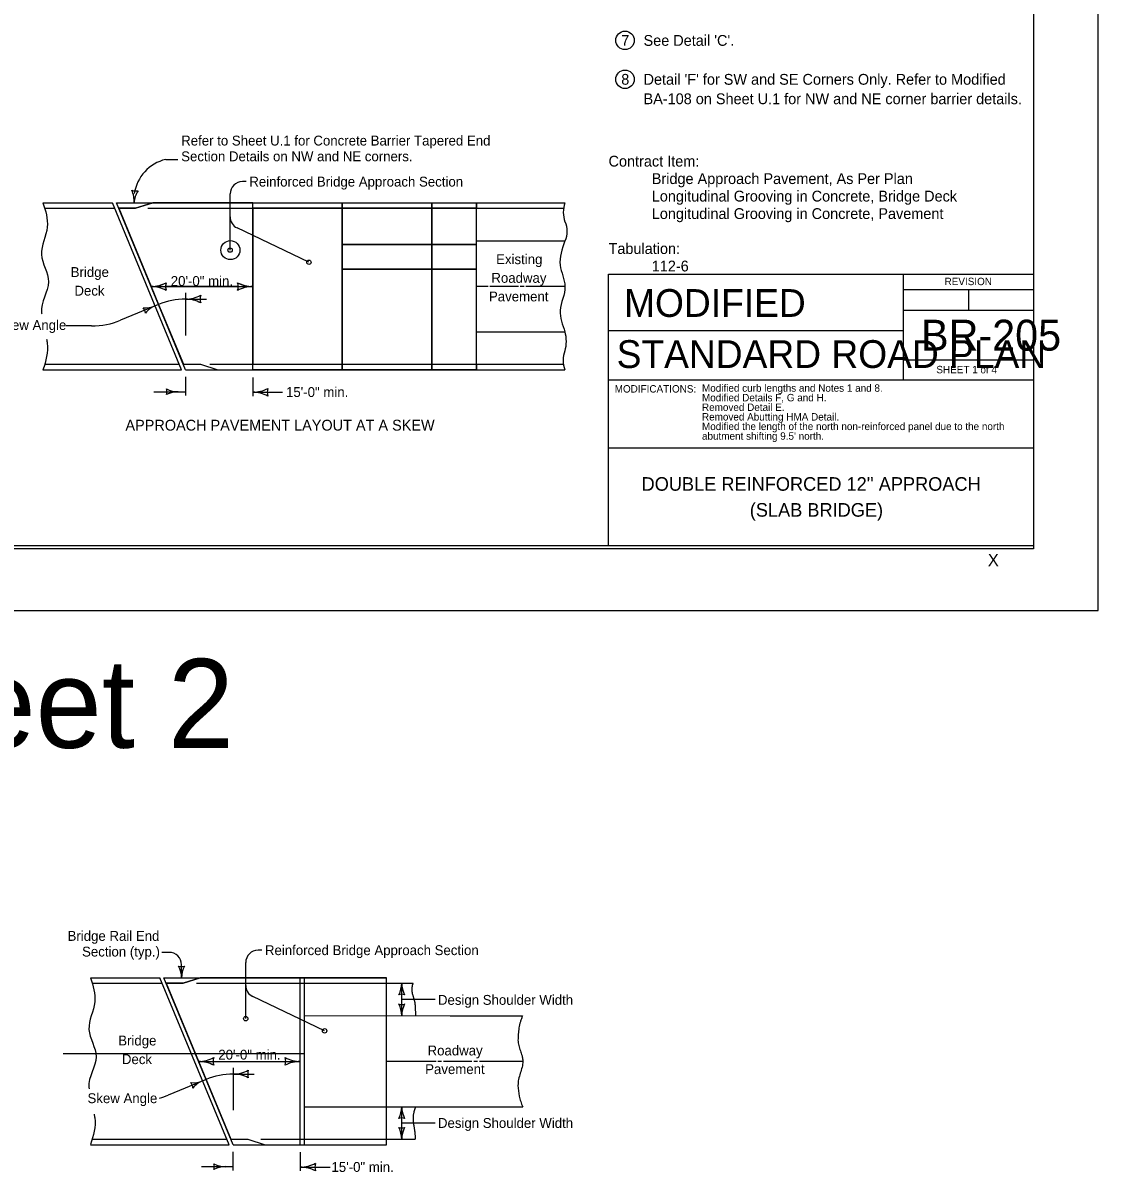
# Model space of a CAD drawing. Extents: x 10028 to 81668, y 6395 to 11634.
# Drawn here: x 15231 to 16972, y 6915 to 8776 of the extents above; entities that cross this region are included whole.
import ezdxf

# ---------------------------------------------------------------- set-up
doc = ezdxf.new("R2010")
doc.units = 0
for name, color, linetype in [('Constructions', 7, 'Continuous'), ('Default', 7, 'Continuous'), ('dsnCellElements', 7, 'Continuous'), ('dsnPaintPlaceStopLineWhite', 7, 'Continuous'), ('dsnstdblockInterim', 7, 'Continuous'), ('dsnStdBlockNotModified', 7, 'Continuous'), ('dsnStdDimension', 7, 'Continuous'), ('dsnStdTextLabel', 7, 'Continuous'), ('dsnStgShadingPropPav', 7, 'Continuous'), ('dsnTextNote', 7, 'Continuous'), ('ShtPlotIdentification', 7, 'Continuous'), ('TextAlignmentSml', 7, 'Continuous')]:
    doc.layers.add(name, color=color, linetype=linetype)

msp = doc.modelspace()

# ---------------------------------------------------------------- linework, layer by layer
at = {"layer": 'Default'}
msp.add_lwpolyline([(13732.5, 9944), (16867.5, 9944), (16867.5, 7924), (13732.5, 7924)], close=True, dxfattribs=at)
at = {"layer": 'dsnCellElements'}
for p, q in [((15893.2, 8475.8), (15748.3, 8475.8)), ((15748.3, 8475.8), (15748.3, 8417.2)), ((15893.2, 8417.2), (15893.2, 8475.8)), ((15965.7, 8475.8), (15893.2, 8475.8)), ((15893.2, 8475.8), (15893.2, 8417.2)), ((15965.7, 8417.2), (15965.7, 8475.8)), ((15893.2, 8417.2), (15748.3, 8417.2)), ((15748.3, 8417.2), (15748.3, 8377.2)), ((15748.3, 8417.2), (15893.2, 8417.2)), ((15893.2, 8377.2), (15893.2, 8417.2)), ((15893.2, 8417.2), (15893.2, 8417.2)), ((15965.7, 8417.2), (15893.2, 8417.2)), ((15893.2, 8417.2), (15893.2, 8377.2)), ((15893.2, 8417.2), (15965.7, 8417.2)), ((15965.7, 8377.2), (15965.7, 8417.2)), ((15748.3, 8377.2), (15748.3, 8223)), ((15748.3, 8377.2), (15893.2, 8377.2)), ((15893.2, 8223), (15893.2, 8377.2)), ((15893.2, 8377.2), (15893.2, 8223)), ((15965.7, 8377.2), (15893.2, 8377.2)), ((15893.2, 8377.2), (15965.7, 8377.2)), ((15965.7, 8223), (15965.7, 8377.2)), ((15748.3, 8223), (15893.2, 8223)), ((15893.2, 8223), (15965.7, 8223))]:
    msp.add_line(p, q, dxfattribs=at)
for points in [[(15603.4, 8484.5), (15748.3, 8484.5), (15748.3, 8475.8), (15628.4, 8475.8), (15603.4, 8475.8)], [(15893.2, 8484.4), (15893.2, 8475.8), (15748.3, 8475.8), (15748.3, 8484.5)], [(15965.7, 8484.4), (15965.7, 8475.8), (15893.2, 8475.8), (15893.2, 8484.4)], [(15748.3, 8214.1), (15603.4, 8214.1), (15603.4, 8223), (15610.7, 8223), (15653.9, 8223), (15701.6, 8223), (15748.3, 8223)], [(15748.3, 8214.1), (15748.3, 8223), (15893.2, 8223), (15893.2, 8214.1)], [(15965.7, 8214.1), (15893.2, 8214.1), (15893.2, 8223), (15965.7, 8223)]]:
    msp.add_lwpolyline(points, close=True, dxfattribs=at)
msp.add_lwpolyline([(15893.2, 8377.2), (15893.2, 8377.2), (15748.3, 8377.2)], dxfattribs=at)
at = {"layer": 'dsnstdblockInterim'}
msp.add_lwpolyline([(13732.5, 9939), (16867.5, 9939), (16867.5, 7929), (13732.5, 7929)], close=True, dxfattribs=at)
at = {"layer": 'dsnStdBlockNotModified'}
for centre, radius, start, end in [((15413.9, 8520), 16.4, 247.9002, 283.3669), ((15368.8, 8487.7), 42.5, 355.6335, 23.706), ((15453.6, 8481.3), 42.5, 147.561, 175.6335)]:
    msp.add_arc(centre, radius, start, end, dxfattribs=at)
at = {"layer": 'dsnStdDimension'}
msp.add_lwpolyline([(13628, 7824.5), (16972, 7824.5), (16972, 10408.5), (13628, 10408.5)], close=True, dxfattribs=at)
at = {"layer": 'dsnStgShadingPropPav'}
for centre in [(15566.8, 8407.9), (15694.4, 8388.2), (15592.1, 7163.5), (15719.8, 7143.8)]:
    msp.add_circle(centre, 3.54, dxfattribs=at)
at = {"layer": 'ShtPlotIdentification'}
for p, q in [((15462.5, 8554.6), (15482, 8554.6)), ((15592.9, 8518.8), (15586.8, 8518.8)), ((15263.8, 8484.5), (15375.9, 8484.5)), ((15488.1, 8214.1), (15376.1, 8484.5)), ((15494.7, 8214.1), (15382.8, 8484.5)), ((15382.8, 8484.5), (15603.4, 8484.5)), ((15441.5, 8484.5), (15413.8, 8475.8)), ((15413.8, 8475.8), (15441.5, 8484.5)), ((15603.4, 8484.5), (15441.5, 8484.5)), ((15566.8, 8407.9), (15566.8, 8498.8)), ((15603.4, 8423.1), (15603.4, 8484.5)), ((15603.4, 8223), (15603.4, 8484.5)), ((15603.4, 8484.5), (15965.7, 8484.4)), ((15748.3, 8214.1), (15748.3, 8484.5)), ((15893.2, 8214.1), (15893.2, 8484.4)), ((15965.7, 8214.1), (15965.7, 8484.4)), ((15965.7, 8484.4), (16109, 8484.4)), ((15266.7, 8475.8), (15379.6, 8475.8)), ((15386.3, 8475.8), (15413.8, 8475.8)), ((15413.8, 8475.8), (15386.4, 8475.8)), ((15386.4, 8475.8), (15438.9, 8349)), ((15433.4, 8475.8), (16106.8, 8475.8)), ((15748.3, 8475.8), (15603.4, 8475.8)), ((15965.7, 8223), (15965.7, 8475.8)), ((15694.4, 8388.2), (15578.1, 8443.8)), ((15965.7, 8423), (16109, 8423)), ((15438.8, 8349), (15603.4, 8349)), ((15438.9, 8349), (15439.5, 8349)), ((15462.4, 8349), (15579.8, 8349)), ((15579.8, 8349), (15462.4, 8349)), ((15494.7, 8338.6), (15494.7, 8269.9)), ((15602.7, 8349), (15603.4, 8349)), ((15603.4, 8349), (15603.4, 8349)), ((15603.4, 8349), (15603.4, 8281)), ((15450.9, 8319.9), (15389.5, 8294.4)), ((15494.7, 8328.6), (15528.7, 8328.6)), ((15342.5, 8285.1), (15301.1, 8285.1)), ((15603.4, 8281), (15603.4, 8223)), ((15603.4, 8214.1), (15603.4, 8281)), ((15965.7, 8275.5), (16109, 8275.5)), ((15263.8, 8214.1), (15488.1, 8214.1)), ((15266.5, 8223), (15484.4, 8223)), ((15491.1, 8223), (15518.6, 8223)), ((15491.1, 8223), (15518.6, 8223)), ((15494.7, 8214.1), (15603.4, 8214.1)), ((15518.6, 8223), (15546.8, 8214.1)), ((15518.6, 8223), (15546.8, 8214.1)), ((15533.8, 8223), (16106.5, 8223)), ((15546.8, 8214.1), (15603.4, 8214.1)), ((15603.4, 8223), (15653.9, 8223)), ((15603.4, 8214.1), (15965.7, 8214.1)), ((15653.9, 8223), (15653.9, 8223)), ((15965.7, 8214.1), (16109, 8214)), ((15494.4, 8202.6), (15494.4, 8172.4)), ((15603.4, 8201.9), (15603.4, 8171.7)), ((15443.4, 8178.6), (15494.4, 8178.6)), ((15603.4, 8177.8), (15651.8, 8177.8)), ((15468.1, 7270.9), (15456.3, 7270.9)), ((15618.3, 7274.4), (15612.1, 7274.4)), ((15488.1, 7229.8), (15488.1, 7250.9)), ((15592.1, 7163.5), (15592.1, 7254.4)), ((15340.8, 7229.8), (15452.9, 7229.8)), ((15343.6, 7221.1), (15456.6, 7221.1)), ((15565, 6959.4), (15453, 7229.8)), ((15571.7, 6959.4), (15459.7, 7229.8)), ((15459.7, 7229.8), (15820.1, 7229.8)), ((15463.2, 7221.1), (15490.8, 7221.1)), ((15490.8, 7221.1), (15518.5, 7229.8)), ((15512.3, 7221.1), (15862.9, 7221.1)), ((15680.4, 7168.4), (15680.4, 7229.8)), ((15687, 6959.4), (15687, 7229.8)), ((15820.1, 6959.4), (15820.1, 7229.8)), ((15844.6, 7168.4), (15844.6, 7221.1)), ((15719.8, 7143.8), (15603.5, 7199.4)), ((15844.6, 7194.8), (15898.6, 7194.8)), ((15680.4, 7020.9), (15680.4, 7168.4)), ((15687, 7168.4), (15923, 7168.3)), ((15923, 7168.3), (16040.3, 7168.3)), ((15296.3, 7107.3), (15687.2, 7107.3)), ((15515.7, 7094.3), (15680.4, 7094.3)), ((15571.7, 7083.9), (15571.7, 7015.2)), ((15571.7, 7073.9), (15605.7, 7073.9)), ((15527.9, 7065.2), (15466.5, 7039.8)), ((15680.4, 6959.4), (15680.4, 7020.9)), ((15687, 7020.9), (15923, 7020.9)), ((15844.6, 6968.3), (15844.6, 7020.9)), ((15923, 7020.9), (16040.7, 7020.8)), ((15844.6, 6994.6), (15898.6, 6994.6)), ((15340.8, 6959.4), (15565, 6959.4)), ((15343.5, 6968.3), (15561.4, 6968.3)), ((15568, 6968.3), (15595.6, 6968.3)), ((15571.7, 6959.4), (15820.1, 6959.4)), ((15595.6, 6968.3), (15623.7, 6959.4)), ((15616.3, 6968.3), (15866.5, 6968.3)), ((15571.3, 6947.9), (15571.3, 6917.7)), ((15680.4, 6947.2), (15680.4, 6917)), ((15520.4, 6923.9), (15571.3, 6923.9)), ((15680.4, 6923.1), (15728.8, 6923.1))]:
    msp.add_line(p, q, dxfattribs=at)
for points in [[(15603.4, 8349), (15603.4, 8408.3), (15603.4, 8423.1), (15603.4, 8475.8), (15603.4, 8484.5)], [(15603.4, 8475.8), (15603.4, 8408.3), (15603.4, 8349)], [(15748.3, 8223), (15748.3, 8349.4), (15748.3, 8475.8)], [(15438.9, 8349), (15450.9, 8319.9), (15491.1, 8223)], [(15603.4, 8214.1), (15603.4, 8223), (15603.4, 8275.6), (15603.4, 8349)], [(15603.4, 8349), (15603.4, 8349)], [(15965.7, 8349.3), (15984.4, 8349.3)], [(15987.5, 8349.3), (16033.5, 8349.3)], [(16036.6, 8349.3), (16042.8, 8349.3)], [(16045.8, 8349.3), (16109, 8349.3)], [(15653.9, 8223), (15701.6, 8223), (15748.3, 8223)], [(15567.9, 6968.3), (15595.5, 6968.3), (15623.6, 6959.4), (15820.1, 6959.4), (15820.1, 7229.8), (15518.4, 7229.8), (15490.7, 7221.1), (15463.2, 7221.1), (15567.9, 6968.3)], [(15820.3, 7094.6), (15900.2, 7094.6)], [(15902.9, 7094.6), (15909.1, 7094.6)], [(15912.1, 7094.6), (15958.2, 7094.6)], [(15961.3, 7094.6), (15967.4, 7094.6)], [(15970.5, 7094.6), (16040.5, 7094.6)]]:
    msp.add_lwpolyline(points, dxfattribs=at)
for centre, radius in [((16206.2, 8747.5), 15), ((16206.2, 8684.5), 15), ((15567.2, 8407.9), 15.4), ((15567.2, 8407.9), 15.4), ((15566.8, 8407.9), 3.54)]:
    msp.add_circle(centre, radius, dxfattribs=at)
for centre, radius, start, end in [((15477.6, 8489.7), 66.7, 103.1177, 171.5172), ((15586.8, 8498.8), 20, 90, 180), ((16150.7, 8469), 44.5, 159.7913, 200.2087), ((15586.8, 8461.8), 20, 180, 244.4655), ((16078.8, 8438.3), 33.9, 333.04, 26.96), ((15438.8, 8401.2), 52.2, 270, 298.0725), ((15438.8, 8401.2), 52.2, 270.8433, 298.0725), ((15482.5, 8349), 20.2, 162.2666, 179.9839), ((15482.5, 8349), 20.2, 162.2666, 197.7334), ((15559.6, 8349), 20.2, 0.0161, 17.7334), ((15603.4, 8401.2), 52.2, 241.9275, 269.1567), ((15559.6, 8349), 20.2, 342.2666, 17.7334), ((15603.4, 8401.2), 52.2, 241.9275, 270), ((15438.8, 8296.7), 52.2, 61.9275, 90), ((15438.8, 8296.7), 52.2, 61.9275, 89.8364), ((15482.5, 8349), 20.2, 179.9839, 197.7334), ((15603.4, 8296.7), 52.2, 90.0176, 118.0725), ((15559.6, 8349), 20.2, 342.2666, 0.0161), ((15603.4, 8296.7), 52.2, 90, 118.0725), ((15603.4, 8401.2), 52.2, 269.9824, 270), ((15429.9, 8354.6), 40.2, 264.4275, 292.5), ((15460.6, 8280.4), 40.2, 112.5, 140.5725), ((15494.7, 8214.1), 114.5, 90, 112.5), ((15494.7, 8380.8), 52.2, 270, 298.0725), ((15494.7, 8380.8), 52.2, 270, 298.0725), ((15494.7, 8276.4), 52.2, 61.9275, 90), ((15494.7, 8276.4), 52.2, 61.9275, 90), ((15538.5, 8328.6), 20.2, 162.2666, 197.7334), ((15538.5, 8328.6), 20.2, 162.2666, 197.7334), ((15414.1, 8304.6), 15.5, 4.7666, 40.2333), ((15342.5, 8408), 122.9, 270, 292.5), ((16055.1, 8260.1), 56.1, 344.1047, 15.8953), ((16147.4, 8229.4), 41.4, 158.1771, 201.8229), ((15613.7, 8223), 40.2, 359.9859, 360), ((15448.9, 8178.6), 15.5, 342.2666, 17.7334), ((15482.6, 8218.7), 40.2, 241.9275, 270), ((15482.6, 8138.4), 40.2, 90, 118.0725), ((15603.4, 8230.1), 52.2, 270, 298.0725), ((15603.4, 8125.6), 52.2, 61.9275, 90), ((15647.2, 8177.8), 20.2, 162.2666, 197.7334), ((15468.1, 7250.9), 20, 0, 90), ((15612.1, 7254.4), 20, 90, 180), ((15488.1, 7263.5), 15.5, 252.2666, 287.7333), ((15448, 7229.8), 40.2, 360, 28.0725), ((15528.3, 7229.8), 40.2, 151.9275, 180), ((15804.4, 7221.1), 40.2, 331.9275, 360), ((15884.8, 7221.1), 40.2, 180, 208.0725), ((15612.1, 7217.4), 20, 180, 244.4655), ((15844.6, 7187.4), 15.5, 72.2666, 107.7334), ((15844.6, 7202), 15.5, 252.2666, 287.7333), ((15804.4, 7168.4), 40.2, 360, 28.0725), ((15884.8, 7168.4), 40.2, 151.9275, 180), ((15515.7, 7146.5), 52.2, 270, 298.0725), ((15515.7, 7042), 52.2, 61.9275, 90), ((15559.5, 7094.3), 20.2, 162.2666, 197.7334), ((15636.6, 7094.3), 20.2, 342.2666, 17.7334), ((15680.4, 7146.5), 52.2, 241.9275, 270), ((15680.4, 7042), 52.2, 90, 118.0725), ((15571.7, 6959.4), 114.5, 90, 112.5), ((15571.7, 7126.1), 52.2, 270, 298.0725), ((15571.7, 7126.1), 52.2, 270, 298.0725), ((15571.7, 7021.7), 52.2, 61.9275, 90), ((15571.7, 7021.7), 52.2, 61.9275, 90), ((15615.5, 7073.9), 20.2, 162.2666, 197.7334), ((15615.5, 7073.9), 20.2, 162.2666, 197.7334), ((15506.8, 7099.9), 40.2, 264.4275, 292.5), ((15491.1, 7049.9), 15.5, 4.7666, 40.2333), ((15537.6, 7025.7), 40.2, 112.5, 140.5725), ((15419.5, 7153.3), 122.9, 285.5345, 292.5), ((15804.4, 7020.9), 40.2, 331.9275, 360), ((15884.8, 7020.9), 40.2, 180, 208.0725), ((15844.6, 6987.2), 15.5, 72.2666, 107.7334), ((15844.6, 7002), 15.5, 252.2666, 287.7333), ((15804.4, 6968.3), 40.2, 360, 28.0725), ((15884.8, 6968.3), 40.2, 151.9275, 180), ((15525.9, 6923.9), 15.5, 342.2666, 17.7334), ((15559.6, 6964), 40.2, 241.9275, 270), ((15559.6, 6883.7), 40.2, 90, 118.0725), ((15680.4, 6975.4), 52.2, 270, 298.0725), ((15680.4, 6870.9), 52.2, 61.9275, 90), ((15724.2, 6923.1), 20.2, 162.2666, 197.7334)]:
    msp.add_arc(centre, radius, start, end, dxfattribs=at)
for points in [[(15263.8, 8484.5), (15270.7, 8445.3), (15261.4, 8400.9), (15272.7, 8356.6), (15261.4, 8307), (15261.7, 8304.7)], [(16109, 8423), (16101.2, 8383.3), (16109, 8349.2), (16101.2, 8310.1), (16109, 8275.5)], [(15269.5, 8263.7), (15270.7, 8257.5), (15263.8, 8214.1)], [(15340.8, 7229.8), (15347.6, 7190.6), (15338.3, 7146.2), (15349.7, 7101.9), (15338.3, 7052.3), (15338.6, 7050)], [(16040.3, 7168.3), (16038.4, 7163.4), (16036.8, 7158.4), (16034.5, 7148.5), (16033.3, 7138.5), (16033, 7133.6), (16032.9, 7128.6), (16033.2, 7124.4), (16034, 7120.1), (16036.7, 7111.6), (16039.4, 7103.1), (16040.5, 7096.7), (16040.6, 7095.6), (16040.7, 7094.6), (16040.4, 7089.7), (16039.4, 7084.8), (16036.6, 7075), (16033.9, 7065.2), (16033.1, 7060.3), (16032.9, 7055.4), (16035, 7038.1), (16037.3, 7029.4), (16038.8, 7025.1), (16040.7, 7020.8)], [(15346.4, 7009), (15347.6, 7002.8), (15340.8, 6959.5)]]:
    msp.add_spline(points, degree=3, dxfattribs=at)
for points in [[(15862.9, 7221.1), (15862.7, 7220.6), (15862.5, 7220.1), (15862.4, 7219.6), (15862.2, 7219.1), (15862.1, 7218.6), (15861.9, 7218.1), (15861.7, 7217.2), (15861.5, 7216.2), (15861.3, 7215.2), (15861.1, 7214.2), (15861, 7213.2), (15861, 7212.2), (15860.9, 7211.7), (15860.9, 7211.2), (15860.9, 7210.7), (15860.9, 7210.2), (15860.9, 7209.7), (15860.9, 7209.2), (15861, 7208.2), (15861.1, 7207.3), (15861.3, 7206.3), (15861.4, 7205.4), (15861.6, 7204.4), (15861.9, 7203.5), (15862.4, 7201.6), (15863, 7199.8), (15863.5, 7197.9), (15864.1, 7196), (15864.6, 7194.1), (15865.2, 7192.2), (15865.5, 7191.3), (15865.6, 7190.3), (15865.8, 7189.4), (15865.9, 7188.4), (15866.1, 7187.4), (15866.1, 7186.5), (15866.2, 7185), (15866.3, 7183.5), (15866.3, 7181.9), (15866.4, 7180.4), (15866.5, 7178.9), (15866.6, 7177.4), (15866.7, 7175.9), (15866.7, 7174.4), (15866.8, 7172.9), (15866.8, 7171.4), (15866.9, 7169.9), (15866.9, 7168.4)], [(15866.9, 7020.9), (15866.6, 7020), (15866.3, 7019.1), (15866, 7018.3), (15865.8, 7017.4), (15865.5, 7016.5), (15865.2, 7015.6), (15864.7, 7013.9), (15864.3, 7012.1), (15863.9, 7010.3), (15863.3, 7007.7), (15863, 7005.1), (15863, 7002.4), (15862.9, 7001.9), (15862.9, 7001.5), (15863, 7001.1), (15863, 7000.6), (15863, 7000.2), (15863, 6999.7), (15863.1, 6998.7), (15863.2, 6997.8), (15863.3, 6996.8), (15863.4, 6995.8), (15863.5, 6994.8), (15863.6, 6993.8), (15863.9, 6991.8), (15864.3, 6989.9), (15864.6, 6987.9), (15864.9, 6985.9), (15865.2, 6983.9), (15865.5, 6982), (15865.7, 6981), (15865.8, 6980), (15865.9, 6979), (15866, 6978), (15866.1, 6977), (15866.1, 6976), (15866.3, 6973.4), (15866.4, 6970.9), (15866.5, 6968.3)]]:
    msp.add_open_spline(points, degree=3, dxfattribs=at)
at = {"layer": 'TextAlignmentSml'}
for p, q in [((16656.6, 8369), (16656.6, 8277.7)), ((16656.6, 8344.1), (16867.5, 8344.1)), ((16762.1, 8344.1), (16762.1, 8310.9)), ((16656.6, 8310.9), (16867.5, 8310.9)), ((16179.5, 8277.7), (16656.6, 8277.7)), ((16656.6, 8277.7), (16656.6, 8197.7)), ((16867.5, 8229.9), (16656.6, 8229.9)), ((16179.5, 8197.7), (16867.5, 8197.7)), ((16179.5, 8087.7), (16867.5, 8087.7))]:
    msp.add_line(p, q, dxfattribs=at)
msp.add_lwpolyline([(16179.5, 8369), (16867.5, 8369), (16867.5, 7929), (16179.5, 7929)], close=True, dxfattribs=at)

# ---------------------------------------------------------------- texts
at = {"layer": 'Constructions'}
msp.add_text('X', height=20, dxfattribs=at).set_placement((16793.6, 7896))
at = {"layer": 'dsnCellElements'}
for s, height, p in [('7', 17.5, (16200.1, 8738.7)), ("See Detail 'C'.", 17.5, (16236.2, 8738.7)), ('8', 17.5, (16200.1, 8675.7)), ("Detail 'F' for SW and SE Corners Only. Refer to Modified ", 17.5, (16236.2, 8675.7)), ('BA-108 on Sheet U.1 for NW and NE corner barrier details.', 17.5, (16236.2, 8644.2)), ('Reinforced Bridge Approach Section', 16, (15597.9, 8510.8)), ('Existing', 16, (15997.5, 8385.2)), ('Bridge', 16, (15308.7, 8364.4)), ('20\'-0" min.', 16, (15470.7, 8349.9)), ('Roadway', 16, (15989.8, 8355)), ('Deck', 16, (15314.7, 8334.2)), ('Pavement', 16, (15985.9, 8324.9)), ('Skew Angle', 16, (15188.6, 8278.6)), ('15\'-0" min.', 16, (15657.3, 8170.1)), ('Reinforced Bridge Approach Section', 16, (15623.2, 7266.4)), ('Design Shoulder Width', 16, (15903.3, 7185.9)), ('Bridge', 16, (15385.6, 7120.1)), ('20\'-0" min.', 16, (15547.7, 7097.2)), ('Roadway', 16, (15886.5, 7104)), ('Deck', 16, (15391.6, 7089.9)), ('Pavement', 16, (15882.6, 7073.8)), ('Skew Angle', 16, (15335.9, 7026.7)), ('Design Shoulder Width', 16, (15903.3, 6986.6)), ('15\'-0" min.', 16, (15730.9, 6915.4))]:
    msp.add_text(s, height=height, dxfattribs=at).set_placement(p)
at = {"layer": 'dsnPaintPlaceStopLineWhite'}
for s, p in [('Contract Item:', (16179.5, 8543.2)), ('Bridge Approach Pavement, As Per Plan', (16249.5, 8514.9)), ('Longitudinal Grooving in Concrete, Bridge Deck', (16249.5, 8486.6)), ('Longitudinal Grooving in Concrete, Pavement', (16249.5, 8458.3)), ('Tabulation:', (16179.5, 8401.7)), ('112-6', (16249.5, 8373.4)), ('112-6', (16249.5, 8373.4))]:
    msp.add_text(s, height=17.5, dxfattribs=at).set_placement(p)
at = {"layer": 'dsnStdTextLabel'}
msp.add_text('Sheet 2', height=144, dxfattribs=at).set_placement((14909.3, 7602))
at = {"layer": 'dsnTextNote'}
for s, height, p in [('MODIFIED', 45, (16204.6, 8299.8)), ('MODIFICATIONS:', 12, (16189.5, 8177.3))]:
    msp.add_text(s, height=height, dxfattribs=at).set_placement(p)
at = {"layer": 'ShtPlotIdentification'}
for s, height, p in [('Refer to Sheet U.1 for Concrete Barrier Tapered End', 16, (15487.6, 8577.3)), ('Section Details on NW and NE corners.', 16, (15487.6, 8551.8)), ('APPROACH PAVEMENT LAYOUT AT A SKEW', 17.5, (15397.3, 8115.7)), ('Bridge Rail End', 16, (15303.6, 7289.5)), ('Section (typ.)', 16, (15327.1, 7264.1))]:
    msp.add_text(s, height=height, dxfattribs=at).set_placement(p)
at = {"layer": 'TextAlignmentSml'}
for s, height, p in [('REVISION', 12, (16723.6, 8351.2)), ('BR-205', 50, (16685.5, 8245.2)), ('STANDARD ROAD PLAN', 45.001, (16192.6, 8217.1)), ('SHEET 1 of 4', 12, (16710.3, 8208.5)), ('Modified curb lengths and Notes 1 and 8.', 12, (16330.8, 8178.6)), ('Modified Details F, G and H.', 12, (16330.8, 8163.1)), ('Removed Detail E.', 12, (16330.8, 8147.5)), ('Removed Abutting HMA Detail.', 12, (16330.8, 8132)), ("abutment shifting 9.5' north.", 12, (16330.8, 8100.9)), ('Modified the length of the north non-reinforced panel due to the north', 12, (16330.8, 8116.5)), ("DOUBLE REINFORCED 12'' APPROACH", 22, (16233, 8018.3)), ('(SLAB BRIDGE)', 22, (16408.2, 7976.3))]:
    msp.add_text(s, height=height, dxfattribs=at).set_placement(p)

doc.saveas('drawing.dxf')
